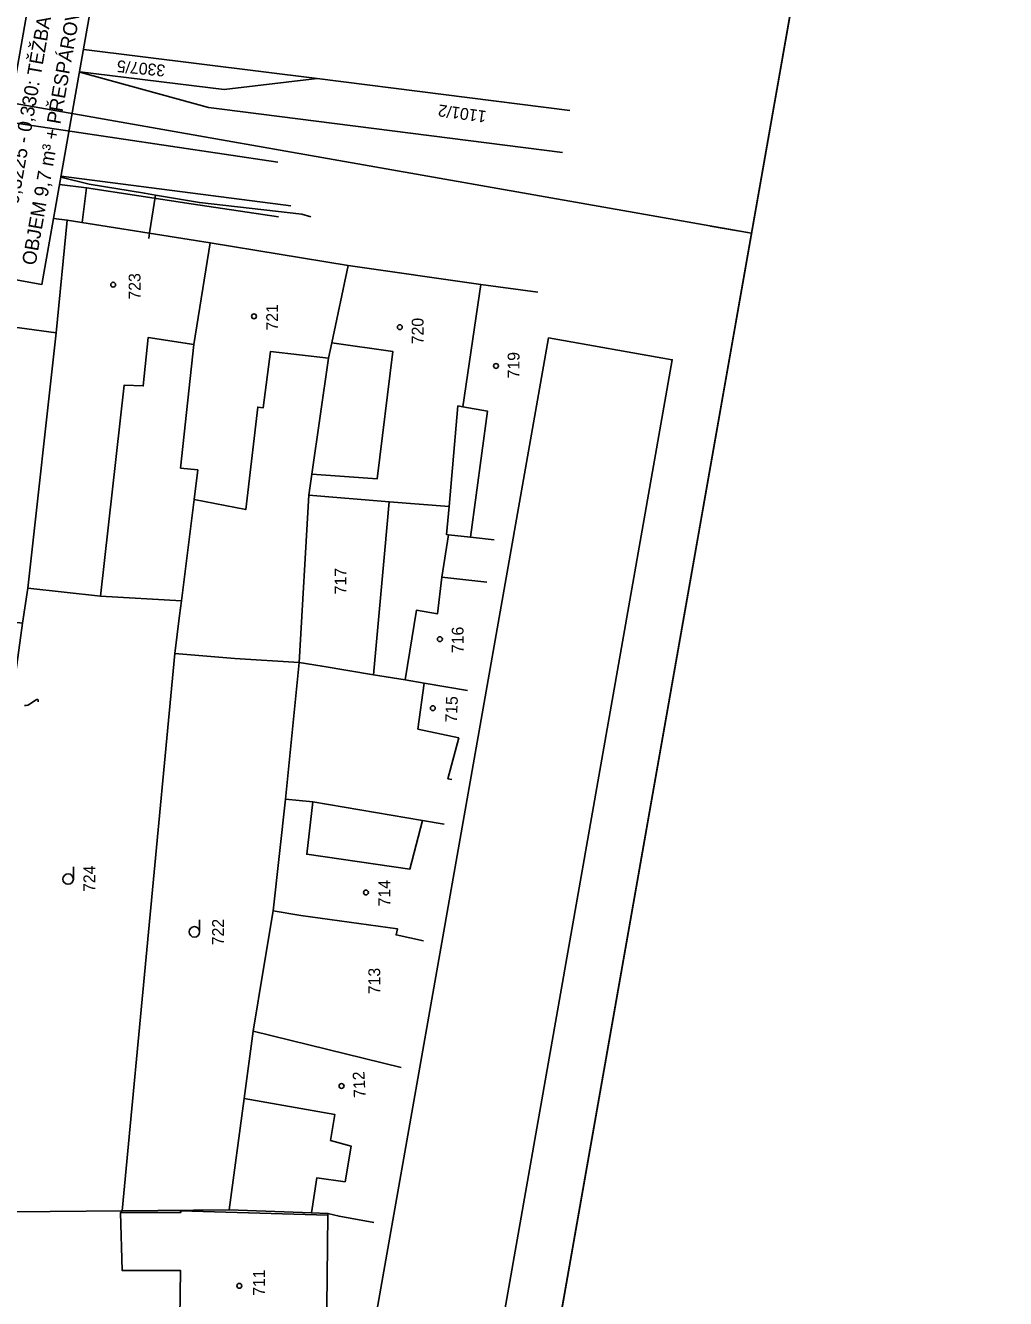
# Model space of a CAD drawing. Extents: x -534481 to -534262, y -1190577 to -1190138.
# Drawn here: x -534332 to -534261.7, y -1190343.4 to -1190251.9 of the extents above; entities that cross this region are included whole.
import ezdxf

# ---------------------------------------------------------------- set-up
doc = ezdxf.new("R2010")
doc.units = 0
for name, color, linetype in [('14', 7, 'Continuous'), ('Definiční body', 7, 'Continuous'), ('Polygon budovy', 7, 'Continuous'), ('Polygon parcely', 7, 'Continuous'), ('Vrstva 1', 7, 'Continuous'), ('Vrstva 19', 7, 'Continuous'), ('Vrstva 30', 7, 'Continuous'), ('Vrstva 31', 7, 'Continuous'), ('Vrstva 35', 7, 'Continuous'), ('Vrstva 43', 7, 'Continuous'), ('Vrstva 46', 7, 'Continuous'), ('Vrstva 48', 7, 'Continuous'), ('Značky bodu BP', 7, 'Continuous')]:
    doc.layers.add(name, color=color, linetype=linetype)

msp = doc.modelspace()

# ---------------------------------------------------------------- linework, layer by layer
at = {"layer": '14'}
for points in [[(-534329.584, -1190263.371), (-534327.65, -1190263.6), (-534320.14, -1190264.75), (-534313.856, -1190265.686)], [(-534327.65, -1190263.6), (-534327.96, -1190266.08)]]:
    msp.add_lwpolyline(points, dxfattribs=at)
at = {"layer": 'Definiční body'}
for p, q in [((-534327.842, -1190253.66), (-534311.1, -1190255.76)), ((-534318.76, -1190267.54), (-534329.03, -1190265.92)), ((-534308.86, -1190269.19), (-534318.76, -1190267.54)), ((-534299.34, -1190270.54), (-534308.86, -1190269.19)), ((-534295.243, -1190271.089), (-534299.34, -1190270.54)), ((-534311.69, -1190285.66), (-534312.39, -1190297.68)), ((-534305.91, -1190286.14), (-534311.69, -1190285.66)), ((-534305.91, -1190286.14), (-534306.23, -1190289.63)), ((-534301.62, -1190286.49), (-534305.91, -1190286.14)), ((-534306.23, -1190289.63), (-534307.05, -1190298.57)), ((-534321.31, -1190297.03), (-534325.09, -1190337.06)), ((-534312.39, -1190297.68), (-534313.35, -1190307.49)), ((-534313.35, -1190307.49), (-534314.25, -1190315.51)), ((-534325.09, -1190337.06), (-534332.83, -1190337.12)), ((-534317.41, -1190337), (-534325.09, -1190337.06))]:
    msp.add_line(p, q, dxfattribs=at)
for points in [[(-534328.129, -1190255.292), (-534318.9, -1190257.84), (-534317.93, -1190257.96), (-534293.474, -1190261.054)], [(-534311.1, -1190255.76), (-534317.76, -1190256.55), (-534328.125, -1190255.269)], [(-534292.945, -1190258.056), (-534311.1, -1190255.76)], [(-534329.03, -1190265.92), (-534330.011, -1190265.792)], [(-534329.03, -1190265.92), (-534329.83, -1190274.01), (-534331.85, -1190292.36)], [(-534318.76, -1190267.54), (-534319.95, -1190274.86), (-534320.89, -1190283.73), (-534319.66, -1190283.86), (-534319.92, -1190285.99), (-534320.83, -1190293.25)], [(-534308.86, -1190269.19), (-534310.04, -1190274.74), (-534310.28, -1190275.84), (-534311.47, -1190284.16), (-534311.69, -1190285.66)], [(-534299.34, -1190270.54), (-534300.62, -1190279.32), (-534300.98, -1190279.26), (-534301.62, -1190286.49)], [(-534301.66, -1190288.52), (-534301.8, -1190288.5), (-534301.62, -1190286.49)], [(-534298.915, -1190291.913), (-534302.14, -1190291.55), (-534301.66, -1190288.52)], [(-534301.66, -1190288.52), (-534300.07, -1190288.69), (-534298.378, -1190288.871)], [(-534331.85, -1190292.36), (-534332.25, -1190294.85), (-534333.12, -1190301.37), (-534333.95, -1190307.91)], [(-534331.85, -1190292.36), (-534326.64, -1190292.92), (-534320.83, -1190293.25)], [(-534320.83, -1190293.25), (-534320.97, -1190294.31), (-534321.31, -1190297.03)], [(-534321.31, -1190297.03), (-534317.01, -1190297.41), (-534312.39, -1190297.68)], [(-534307.05, -1190298.57), (-534310.73, -1190297.96), (-534312.39, -1190297.68)], [(-534300.285, -1190299.686), (-534303.4, -1190299.17), (-534304.76, -1190298.94), (-534307.05, -1190298.57)], [(-534301.981, -1190309.302), (-534303.52, -1190309.04), (-534311.4, -1190307.7), (-534313.35, -1190307.49)], [(-534314.25, -1190315.51), (-534314.94, -1190319.65), (-534315.69, -1190324.17)], [(-534303.455, -1190317.663), (-534305.42, -1190317.25), (-534305.33, -1190316.8), (-534312.25, -1190315.85), (-534314.25, -1190315.51)], [(-534315.69, -1190324.17), (-534316.34, -1190328.99), (-534317.41, -1190337)], [(-534305.061, -1190326.768), (-534315.69, -1190324.17)], [(-534310.32, -1190337.25), (-534311.5, -1190337.21), (-534317.41, -1190337)], [(-534315.73, -1190352.48), (-534310.81, -1190348.3), (-534310.45, -1190348.3), (-534310.32, -1190337.38), (-534310.32, -1190337.25)], [(-534310.32, -1190337.25), (-534309.51, -1190337.45), (-534307.024, -1190337.904)]]:
    msp.add_lwpolyline(points, dxfattribs=at)
at = {"layer": 'Polygon parcely'}
for p, q in [((-534298.378, -1190288.871), (-534298.378, -1190288.871)), ((-534300.285, -1190299.686), (-534300.285, -1190299.686)), ((-534303.455, -1190317.663), (-534303.455, -1190317.663)), ((-534307.024, -1190337.904), (-534307.024, -1190337.904))]:
    msp.add_line(p, q, dxfattribs=at)
for points in [[(-534334.434, -1190265.214), (-534341.12, -1190264.34), (-534341.18, -1190264.8), (-534342.09, -1190272.42), (-534339.77, -1190272.69), (-534343.2, -1190300.17), (-534333.12, -1190301.37), (-534332.25, -1190294.85), (-534337.72, -1190294.22), (-534334.94, -1190273.31), (-534329.83, -1190274.01), (-534329.03, -1190265.92), (-534330.011, -1190265.792)], [(-534295.243, -1190271.089), (-534299.34, -1190270.54), (-534300.62, -1190279.32), (-534298.85, -1190279.64), (-534300.07, -1190288.69), (-534298.378, -1190288.871)], [(-534298.915, -1190291.913), (-534302.14, -1190291.55), (-534302.44, -1190294.18), (-534303.96, -1190293.94), (-534304.76, -1190298.94), (-534303.4, -1190299.17), (-534300.285, -1190299.686)], [(-534300.285, -1190299.686), (-534303.4, -1190299.17), (-534303.85, -1190302.47), (-534300.92, -1190303.1), (-534301.7, -1190306.03), (-534301.413, -1190306.078)], [(-534301.981, -1190309.302), (-534303.52, -1190309.04), (-534304.43, -1190312.52), (-534311.84, -1190311.46), (-534311.4, -1190307.7), (-534313.35, -1190307.49), (-534314.25, -1190315.51), (-534312.25, -1190315.85), (-534305.33, -1190316.8), (-534305.42, -1190317.25), (-534303.455, -1190317.663)], [(-534305.061, -1190326.768), (-534315.69, -1190324.17), (-534316.34, -1190328.99), (-534309.81, -1190330.15), (-534310.13, -1190332), (-534308.64, -1190332.42), (-534309.09, -1190334.97), (-534311.12, -1190334.7), (-534311.5, -1190337.21), (-534310.32, -1190337.25), (-534309.51, -1190337.45), (-534307.024, -1190337.904)]]:
    msp.add_lwpolyline(points, dxfattribs=at)
for points in [[(-534329.03, -1190265.92), (-534329.83, -1190274.01), (-534331.85, -1190292.36), (-534326.64, -1190292.92), (-534324.94, -1190277.76), (-534323.57, -1190277.82), (-534323.23, -1190274.35), (-534319.95, -1190274.86), (-534318.76, -1190267.54)], [(-534319.92, -1190285.99), (-534316.22, -1190286.71), (-534315.36, -1190279.35), (-534314.97, -1190279.41), (-534314.43, -1190275.35), (-534310.28, -1190275.84), (-534310.04, -1190274.74), (-534308.86, -1190269.19), (-534318.76, -1190267.54), (-534319.95, -1190274.86), (-534320.89, -1190283.73), (-534319.66, -1190283.86)], [(-534311.69, -1190285.66), (-534305.91, -1190286.14), (-534301.62, -1190286.49), (-534300.98, -1190279.26), (-534300.62, -1190279.32), (-534299.34, -1190270.54), (-534308.86, -1190269.19), (-534310.04, -1190274.74), (-534305.65, -1190275.36), (-534306.77, -1190284.49), (-534311.47, -1190284.16)], [(-534320.89, -1190337.07), (-534320.88, -1190337.18), (-534325.2, -1190337.17), (-534325.09, -1190341.34), (-534320.9, -1190341.35), (-534320.99, -1190348.17), (-534318.18, -1190348.21), (-534317.67, -1190349.12), (-534315.85, -1190349.15), (-534315.3, -1190348.25), (-534310.81, -1190348.3), (-534310.45, -1190348.3), (-534310.32, -1190337.38)]]:
    msp.add_lwpolyline(points, close=True, dxfattribs=at)
at = {"layer": 'Vrstva 1'}
for points in [[(-534329.491, -1190262.84), (-534327.45, -1190263.33)], [(-534329.491, -1190262.84), (-534327.45, -1190263.33), (-534323.495, -1190263.995), (-534322.692, -1190264.13)], [(-534312.982, -1190264.901), (-534329.478, -1190262.769)], [(-534323.185, -1190267.23), (-534323.122, -1190266.835), (-534322.692, -1190264.13)], [(-534322.692, -1190264.13), (-534319.54, -1190264.66), (-534312.19, -1190265.5), (-534311.55, -1190265.69)]]:
    msp.add_lwpolyline(points, dxfattribs=at)
at = {"layer": 'Vrstva 19'}
msp.add_lwpolyline([(-534332.097, -1190300.767), (-534331.981, -1190300.776), (-534331.867, -1190300.751), (-534331.755, -1190300.692), (-534331.313, -1190300.387), (-534331.218, -1190300.337), (-534331.152, -1190300.34), (-534331.115, -1190300.395), (-534331.109, -1190300.503)], dxfattribs=at)
at = {"layer": 'Vrstva 30'}
for p, q in [((-534279.901, -1190266.866), (-534261.668, -1190163.461)), ((-534298.134, -1190370.27), (-534279.901, -1190266.866))]:
    msp.add_line(p, q, dxfattribs=at)
for points in [[(-534407.912, -1190137.674), (-534480.845, -1190551.293), (-534334.601, -1190577.08), (-534261.668, -1190163.461)], [(-534261.668, -1190163.461), (-534407.912, -1190137.674), (-534426.145, -1190241.079), (-534279.901, -1190266.866)], [(-534279.901, -1190266.866), (-534426.145, -1190241.079), (-534444.378, -1190344.484), (-534298.134, -1190370.27)]]:
    msp.add_lwpolyline(points, dxfattribs=at)
at = {"layer": 'Vrstva 31'}
msp.add_lwpolyline([(-534329.865, -1190239.303), (-534335.236, -1190269.762), (-534330.848, -1190270.536), (-534325.477, -1190240.077)], close=True, dxfattribs=at)
at = {"layer": 'Vrstva 35'}
msp.add_lwpolyline([(-534367.462, -1190255.872), (-534340.907, -1190257.743), (-534313.909, -1190261.752)], dxfattribs=at)
at = {"layer": 'Vrstva 43'}
msp.add_line((-534282.856, -1190266.345), (-534279.901, -1190266.866), dxfattribs=at)
msp.add_lwpolyline([(-534480.845, -1190551.293), (-534334.601, -1190577.08), (-534261.668, -1190163.461)], dxfattribs=at)
at = {"layer": 'Vrstva 46'}
for centre in [(-534325.734, -1190270.561), (-534315.624, -1190272.83), (-534305.15, -1190273.607), (-534298.249, -1190276.391), (-534302.277, -1190296.012), (-534302.786, -1190300.964), (-534307.587, -1190314.203), (-534309.337, -1190328.098), (-534316.673, -1190342.442)]:
    msp.add_circle(centre, 0.175, dxfattribs=at)
at = {"layer": 'Vrstva 48'}
for p, q in [((-534328.593, -1190313.24), (-534328.593, -1190312.365)), ((-534319.53, -1190317.029), (-534319.53, -1190316.154))]:
    msp.add_line(p, q, dxfattribs=at)
for centre in [(-534328.968, -1190313.24), (-534319.905, -1190317.028)]:
    msp.add_circle(centre, 0.375, dxfattribs=at)
at = {"layer": 'Značky bodu BP'}
msp.add_lwpolyline([(-534300.378, -1190359.794), (-534285.593, -1190275.942), (-534294.476, -1190274.376), (-534309.262, -1190358.228)], close=True, dxfattribs=at)

# ---------------------------------------------------------------- texts
at = {"layer": 'Polygon budovy'}
for s, rotation, p in [('3307/5', 174.33625, (-534321.96, -1190254.777)), ('1101/2', 172, (-534298.895, -1190258.092)), ('723', 90, (-534323.771, -1190271.628)), ('721', 90, (-534313.896, -1190273.849)), ('720', 90, (-534303.453, -1190274.834)), ('719', 90, (-534296.563, -1190277.287)), ('717', 90, (-534308.988, -1190292.79)), ('716', 90, (-534300.578, -1190297.011)), ('715', 88, (-534301.051, -1190302.015)), ('724', 90, (-534327.02, -1190314.164)), ('714', 90, (-534305.836, -1190315.203)), ('722', 90, (-534317.781, -1190317.992)), ('713', 90, (-534306.564, -1190321.507)), ('712', 93, (-534307.601, -1190328.918)), ('711', 90, (-534314.841, -1190343.164))]:
    msp.add_text(s, height=0.85, rotation=rotation, dxfattribs=at).set_placement(p)
at = {"layer": 'Vrstva 31'}
for s, p in [('Ř. KM 0,3225 - 0,330: TĚŽBA SEDIMENTU ', (-534333.264, -1190268.867)), ('OBJEM 9,7 m³ + PŘESPÁROVÁNÍ DLAŽBY', (-534331.31, -1190269.211))]:
    msp.add_text(s, height=1, rotation=80.02054, dxfattribs=at).set_placement(p)

doc.saveas('drawing.dxf')
